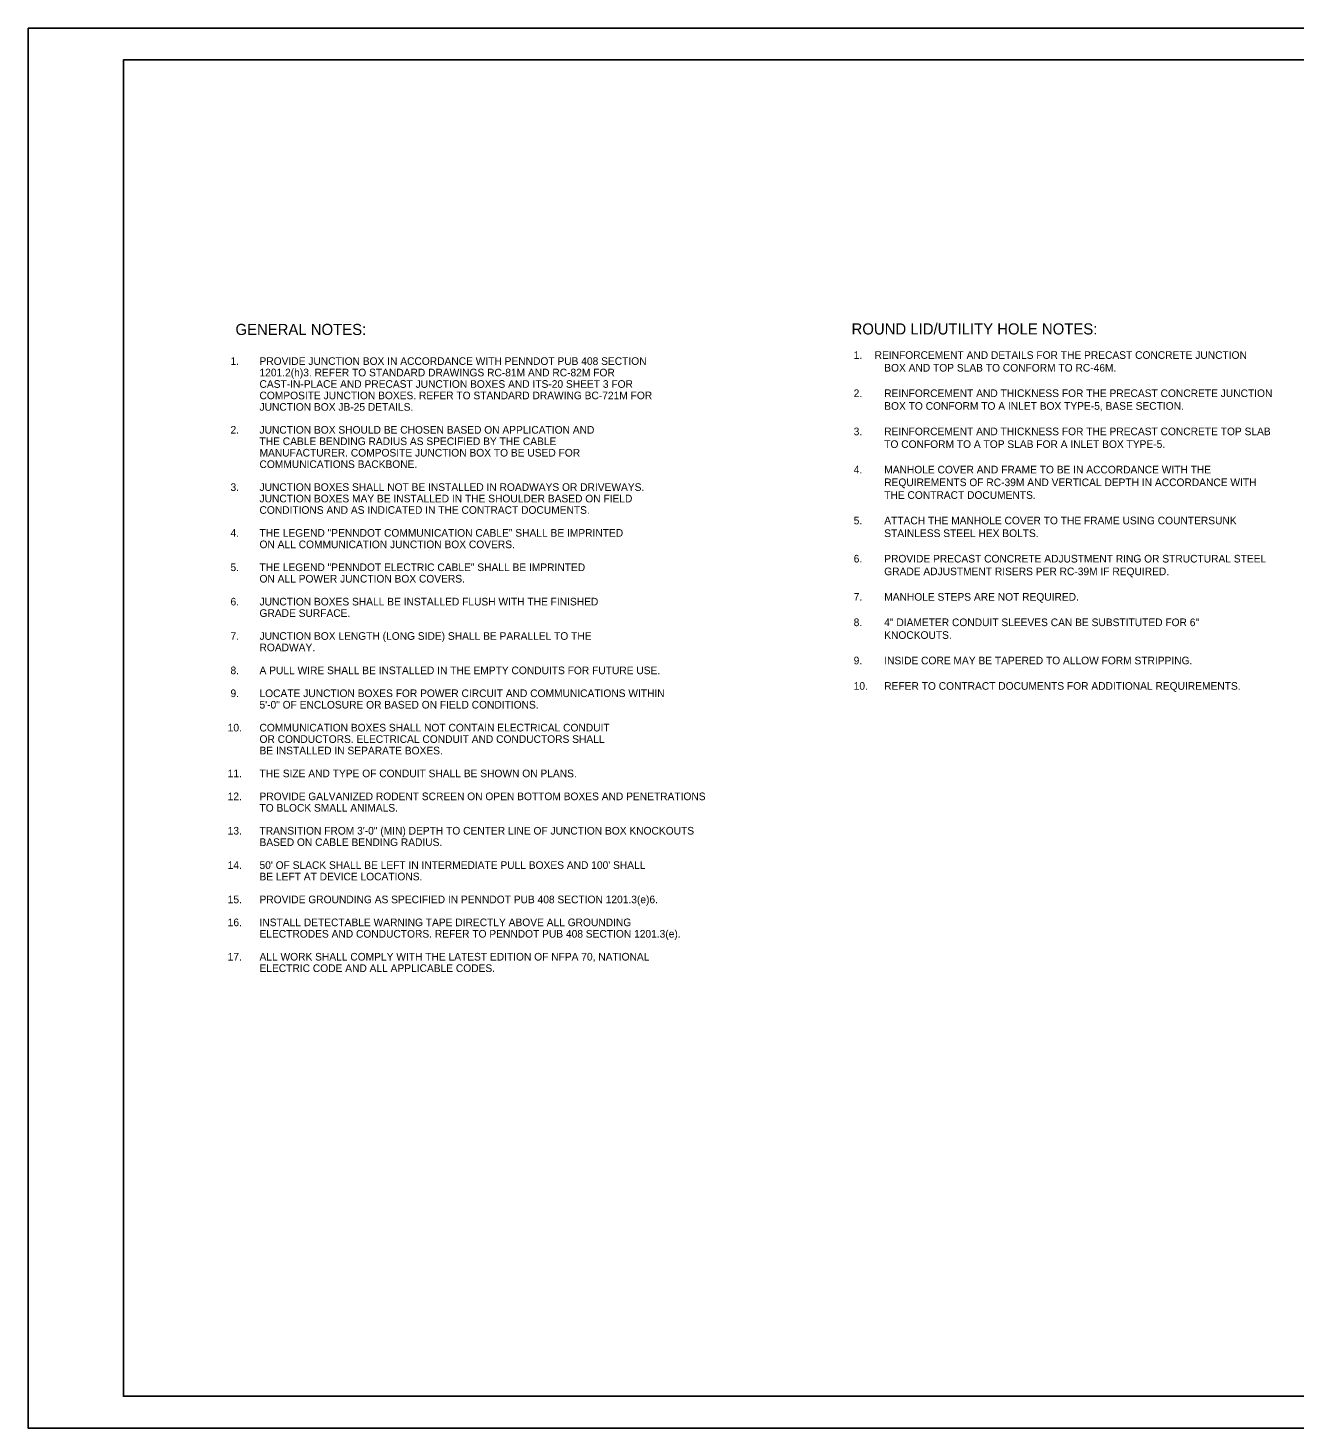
# Model space of a CAD drawing. Extents: x 1299104.8 to 1299141.6, y 239639.8 to 239661.8.
# Drawn here: x 1299104.8 to 1299124.71, y 239639.79 to 239661.79 of the extents above; entities that cross this region are included whole.
import ezdxf

# ---------------------------------------------------------------- set-up
doc = ezdxf.new("R2010")
doc.units = 0
for name, color, linetype in [('DIM TXT', 7, 'Continuous'), ('GS_plotshape_p', 7, 'Continuous'), ('Level 1', 7, 'Continuous'), ('PTEXT', 7, 'Continuous')]:
    doc.layers.add(name, color=color, linetype=linetype)

msp = doc.modelspace()

# ---------------------------------------------------------------- linework, layer by layer
at = {"layer": 'GS_plotshape_p'}
msp.add_lwpolyline([(1299104.802, 239661.791), (1299138.802, 239661.791), (1299138.802, 239639.791), (1299104.802, 239639.791)], close=True, dxfattribs=at)
at = {"layer": 'Level 1'}
msp.add_lwpolyline([(1299138.302, 239640.291), (1299106.302, 239640.291), (1299106.302, 239661.291), (1299138.302, 239661.291)], close=True, dxfattribs=at)

# ---------------------------------------------------------------- texts
at = {"layer": 'DIM TXT'}
for s, height, p in [('GENERAL NOTES:', 0.175, (1299108.061, 239656.967)), (' 1.', 0.12, (1299107.939, 239656.497)), ('PROVIDE JUNCTION BOX IN ACCORDANCE WITH PENNDOT PUB 408 SECTION', 0.12, (1299108.439, 239656.497)), ('1201.2(h)3. REFER TO STANDARD DRAWINGS RC-81M AND RC-82M FOR ', 0.12, (1299108.439, 239656.317)), ('CAST-IN-PLACE AND PRECAST JUNCTION BOXES AND ITS-20 SHEET 3 FOR ', 0.12, (1299108.439, 239656.137)), ('COMPOSITE JUNCTION BOXES. REFER TO STANDARD DRAWING BC-721M FOR ', 0.12, (1299108.439, 239655.957)), ('JUNCTION BOX JB-25 DETAILS.', 0.12, (1299108.439, 239655.777)), (' 2.', 0.12, (1299107.939, 239655.417)), ('JUNCTION BOX SHOULD BE CHOSEN BASED ON APPLICATION AND', 0.12, (1299108.439, 239655.417)), ('THE CABLE BENDING RADIUS AS SPECIFIED BY THE CABLE', 0.12, (1299108.439, 239655.237)), ('MANUFACTURER. COMPOSITE JUNCTION BOX TO BE USED FOR ', 0.12, (1299108.439, 239655.057)), ('COMMUNICATIONS BACKBONE. ', 0.12, (1299108.439, 239654.877)), (' 3.', 0.12, (1299107.939, 239654.517)), ('JUNCTION BOXES SHALL NOT BE INSTALLED IN ROADWAYS OR DRIVEWAYS.', 0.12, (1299108.439, 239654.517)), ('JUNCTION BOXES MAY BE INSTALLED IN THE SHOULDER BASED ON FIELD', 0.12, (1299108.439, 239654.337)), ('CONDITIONS AND AS INDICATED IN THE CONTRACT DOCUMENTS.', 0.12, (1299108.439, 239654.157)), (' 4.', 0.12, (1299107.939, 239653.797)), ('THE LEGEND "PENNDOT COMMUNICATION CABLE" SHALL BE IMPRINTED ', 0.12, (1299108.439, 239653.797)), ('ON ALL COMMUNICATION JUNCTION BOX COVERS.', 0.12, (1299108.439, 239653.617)), (' 5.', 0.12, (1299107.939, 239653.257)), ('THE LEGEND "PENNDOT ELECTRIC CABLE" SHALL BE IMPRINTED ', 0.12, (1299108.439, 239653.257)), ('ON ALL POWER JUNCTION BOX COVERS.', 0.12, (1299108.439, 239653.077)), (' 6.', 0.12, (1299107.939, 239652.717)), ('JUNCTION BOXES SHALL BE INSTALLED FLUSH WITH THE FINISHED ', 0.12, (1299108.439, 239652.717)), ('GRADE SURFACE.', 0.12, (1299108.439, 239652.537)), (' 7.', 0.12, (1299107.939, 239652.177)), ('JUNCTION BOX LENGTH (LONG SIDE) SHALL BE PARALLEL TO THE', 0.12, (1299108.439, 239652.177)), ('ROADWAY.', 0.12, (1299108.439, 239651.997)), (' 8.', 0.12, (1299107.939, 239651.637)), ('A PULL WIRE SHALL BE INSTALLED IN THE EMPTY CONDUITS FOR FUTURE USE.', 0.12, (1299108.439, 239651.637)), (' 9.', 0.12, (1299107.939, 239651.277)), ('LOCATE JUNCTION BOXES FOR POWER CIRCUIT AND COMMUNICATIONS WITHIN', 0.12, (1299108.439, 239651.277)), ('5\'-0" OF ENCLOSURE OR BASED ON FIELD CONDITIONS.', 0.12, (1299108.439, 239651.097)), ('10.', 0.12, (1299107.939, 239650.737)), ('COMMUNICATION BOXES SHALL NOT CONTAIN ELECTRICAL CONDUIT', 0.12, (1299108.439, 239650.737)), ('OR CONDUCTORS. ELECTRICAL CONDUIT AND CONDUCTORS SHALL', 0.12, (1299108.439, 239650.557)), ('BE INSTALLED IN SEPARATE BOXES.', 0.12, (1299108.439, 239650.377)), ('11.', 0.12, (1299107.939, 239650.017)), ('THE SIZE AND TYPE OF CONDUIT SHALL BE SHOWN ON PLANS.', 0.12, (1299108.439, 239650.017)), ('12.', 0.12, (1299107.939, 239649.657)), ('PROVIDE GALVANIZED RODENT SCREEN ON OPEN BOTTOM BOXES AND PENETRATIONS ', 0.12, (1299108.439, 239649.657)), ('TO BLOCK SMALL ANIMALS. ', 0.12, (1299108.439, 239649.477)), ('13.', 0.12, (1299107.939, 239649.117)), ('TRANSITION FROM 3\'-0" (MIN) DEPTH TO CENTER LINE OF JUNCTION BOX KNOCKOUTS', 0.12, (1299108.439, 239649.117)), ('BASED ON CABLE BENDING RADIUS.', 0.12, (1299108.439, 239648.937)), ('14.', 0.12, (1299107.939, 239648.577)), ("50' OF SLACK SHALL BE LEFT IN INTERMEDIATE PULL BOXES AND 100' SHALL", 0.12, (1299108.439, 239648.577)), ('BE LEFT AT DEVICE LOCATIONS. ', 0.12, (1299108.439, 239648.397)), ('15.', 0.12, (1299107.939, 239648.037)), ('PROVIDE GROUNDING AS SPECIFIED IN PENNDOT PUB 408 SECTION 1201.3(e)6.', 0.12, (1299108.439, 239648.037)), ('16.', 0.12, (1299107.939, 239647.677)), ('INSTALL DETECTABLE WARNING TAPE DIRECTLY ABOVE ALL GROUNDING', 0.12, (1299108.439, 239647.677)), ('ELECTRODES AND CONDUCTORS. REFER TO PENNDOT PUB 408 SECTION 1201.3(e).', 0.12, (1299108.439, 239647.497)), ('17.', 0.12, (1299107.939, 239647.137)), ('ALL WORK SHALL COMPLY WITH THE LATEST EDITION OF NFPA 70, NATIONAL ', 0.12, (1299108.439, 239647.137)), ('ELECTRIC CODE AND ALL APPLICABLE CODES. ', 0.12, (1299108.439, 239646.957))]:
    msp.add_text(s, height=height, dxfattribs=at).set_placement(p)
at = {"layer": 'PTEXT'}
for s, height, p in [('ROUND LID/UTILITY HOLE NOTES:', 0.175, (1299117.741, 239656.975)), ('1.', 0.12, (1299117.774, 239656.592)), ('  REINFORCEMENT AND DETAILS FOR THE PRECAST CONCRETE JUNCTION ', 0.12, (1299118.014, 239656.592)), ('BOX AND TOP SLAB TO CONFORM TO RC-46M.', 0.12, (1299118.254, 239656.392)), ('2.', 0.12, (1299117.774, 239655.992)), ('REINFORCEMENT AND THICKNESS FOR THE PRECAST CONCRETE JUNCTION ', 0.12, (1299118.254, 239655.992)), ('BOX TO CONFORM TO A INLET BOX TYPE-5, BASE SECTION.', 0.12, (1299118.254, 239655.792)), ('3.', 0.12, (1299117.774, 239655.392)), ('REINFORCEMENT AND THICKNESS FOR THE PRECAST CONCRETE TOP SLAB ', 0.12, (1299118.254, 239655.392)), ('TO CONFORM TO A TOP SLAB FOR A INLET BOX TYPE-5.', 0.12, (1299118.254, 239655.192)), ('4.', 0.12, (1299117.774, 239654.792)), ('MANHOLE COVER AND FRAME TO BE IN ACCORDANCE WITH THE ', 0.12, (1299118.254, 239654.792)), ('REQUIREMENTS OF RC-39M AND VERTICAL DEPTH IN ACCORDANCE WITH ', 0.12, (1299118.254, 239654.592)), ('THE CONTRACT DOCUMENTS.', 0.12, (1299118.254, 239654.392)), ('5.', 0.12, (1299117.774, 239653.992)), ('ATTACH THE MANHOLE COVER TO THE FRAME USING COUNTERSUNK ', 0.12, (1299118.254, 239653.992)), ('STAINLESS STEEL HEX BOLTS.', 0.12, (1299118.254, 239653.792)), ('6.', 0.12, (1299117.774, 239653.392)), ('PROVIDE PRECAST CONCRETE ADJUSTMENT RING OR STRUCTURAL STEEL ', 0.12, (1299118.254, 239653.392)), ('GRADE ADJUSTMENT RISERS PER RC-39M IF REQUIRED.', 0.12, (1299118.254, 239653.192)), ('7.', 0.12, (1299117.774, 239652.792)), ('MANHOLE STEPS ARE NOT REQUIRED.', 0.12, (1299118.254, 239652.792)), ('8.', 0.12, (1299117.774, 239652.392)), ('4" DIAMETER CONDUIT SLEEVES CAN BE SUBSTITUTED FOR 6" ', 0.12, (1299118.254, 239652.392)), ('KNOCKOUTS.', 0.12, (1299118.254, 239652.192)), ('9.', 0.12, (1299117.774, 239651.792)), ('INSIDE CORE MAY BE TAPERED TO ALLOW FORM STRIPPING.', 0.12, (1299118.254, 239651.792)), ('10.', 0.12, (1299117.774, 239651.392)), ('REFER TO CONTRACT DOCUMENTS FOR ADDITIONAL REQUIREMENTS.', 0.12, (1299118.254, 239651.392))]:
    msp.add_text(s, height=height, dxfattribs=at).set_placement(p)

doc.saveas('drawing.dxf')
